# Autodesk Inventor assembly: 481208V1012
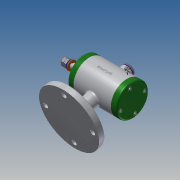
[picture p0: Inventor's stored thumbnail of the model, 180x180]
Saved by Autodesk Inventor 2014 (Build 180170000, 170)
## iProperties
Created: 2018-12
Part Number: 481208V1012
Document SubType Name: Assembly
Designer: 601-24
Author: 601-24
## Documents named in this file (16)
- C:\Users\601-24\Desktop\481208V1012\답안조립품.iam
- C:\Users\601-24\Desktop\481208V1012\481208V1012.ipt
- C:\Users\601-24\Desktop\481208V1012\V벨트풀리.ipt
- C:\Users\601-24\Desktop\481208V1012\고무캡.ipt
- C:\Users\601-24\Desktop\481208V1012\너트 M8.ipt
- 너트 M8.ipt
- C:\Users\601-24\Desktop\481208V1012\뒤커버.ipt
- C:\Users\601-24\Desktop\481208V1012\베어링 15 x 32 x 9.ipt
- C:\Users\601-24\Desktop\481208V1012\볼트 M4 x 12.ipt
- C:\Users\601-24\Desktop\481208V1012\스프링와셔 8.ipt
- C:\Users\601-24\Desktop\481208V1012\앞커버.ipt
- C:\Users\601-24\Desktop\481208V1012\오일 실 15 25 7.ipt
- C:\Users\601-24\Desktop\481208V1012\와셔 8x17.ipt
- C:\Users\601-24\Desktop\481208V1012\축.ipt
- C:\Users\601-24\Desktop\481208V1012\키 3 x 3 x 12.ipt
- C:\Users\601-24\Desktop\481208V1012\본체.ipt
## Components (3 placed, 3 different names)
1. 481208V1012:1
2. V벨트풀리:1 — 각도:2
3. 고무캡:1 — 각도:4, 각도:5
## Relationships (3: Angle 3)
- 각도:2 [Angle]: V벨트풀리:1
- 각도:4 [Angle]: 고무캡:1
- 각도:5 [Angle]: 고무캡:1
